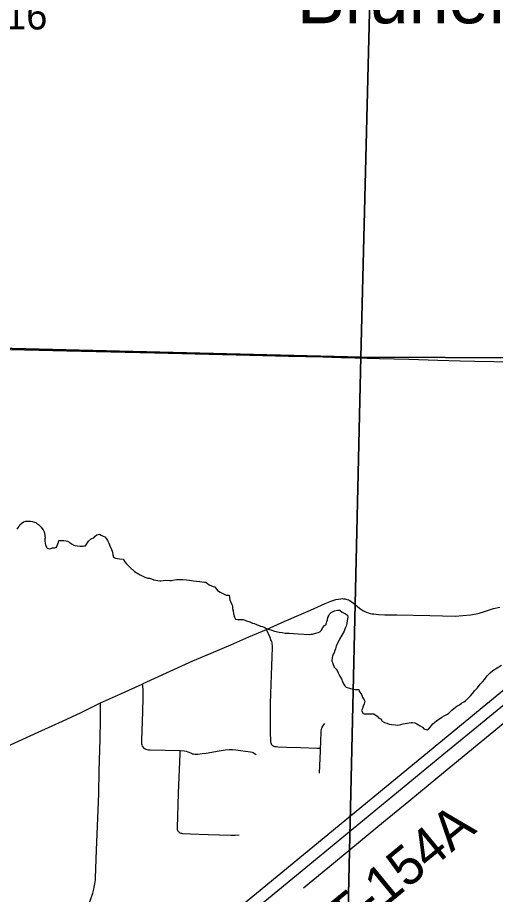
# Model space of a CAD drawing. Extents: x 0 to 34, y 0 to 22.
# Drawn here: x 3.956 to 4.659, y 18.651 to 19.941 of the extents above; entities that cross this region are included whole.
import ezdxf

# ---------------------------------------------------------------- set-up
doc = ezdxf.new("R2010")
doc.units = 0
for name, color, linetype in [('GM_X_Minor_River', 7, 'Continuous'), ('GM_X_Section', 7, 'Continuous'), ('GM_X_Section_Text', 7, 'Continuous'), ('GM_X_Township_Road', 7, 'Continuous'), ('GM_X_Township_Road_Text', 7, 'Continuous'), ('GM_X_Unincorporated_Text', 7, 'Continuous'), ('GM_X_US_Route', 7, 'Continuous')]:
    doc.layers.add(name, color=color, linetype=linetype)

msp = doc.modelspace()

# ---------------------------------------------------------------- linework, layer by layer
at = {"layer": 'GM_X_Minor_River'}
for points in [[(3.9553, 19.1884), (3.958, 19.1921), (3.9596, 19.1947), (3.9627, 19.1981), (3.9647, 19.1992), (3.9681, 19.2002), (3.97, 19.2002), (3.9723, 19.2001), (3.9749, 19.2001), (3.9776, 19.1996), (3.981, 19.1988), (3.9829, 19.1983), (3.9847, 19.1964), (3.987, 19.1952), (3.9888, 19.1933), (3.9907, 19.1917), (3.9918, 19.1898), (3.9936, 19.1874), (3.9951, 19.1847), (3.9961, 19.1794), (3.9964, 19.176), (3.9963, 19.1741), (3.9962, 19.1707), (3.9966, 19.168), (3.9969, 19.1649), (3.9994, 19.1607), (4.0036, 19.1595), (4.0074, 19.1609), (4.0104, 19.1612), (4.0131, 19.1619), (4.0143, 19.1645), (4.016, 19.1694), (4.0168, 19.1717)], [(4.0168, 19.1717), (4.0202, 19.1719), (4.024, 19.1719), (4.0274, 19.1714), (4.0293, 19.171), (4.0327, 19.169), (4.0353, 19.167), (4.0386, 19.165), (4.0409, 19.1646), (4.0439, 19.1638), (4.0481, 19.1636), (4.0515, 19.1636), (4.0534, 19.1639), (4.0557, 19.1642), (4.0601, 19.1709), (4.0647, 19.1746), (4.0682, 19.176), (4.0701, 19.1783), (4.0728, 19.1801), (4.0767, 19.1812), (4.0789, 19.1796), (4.0819, 19.1784), (4.0845, 19.1772), (4.0867, 19.1744), (4.0882, 19.1717), (4.09, 19.1679), (4.0921, 19.1629), (4.0939, 19.1587), (4.095, 19.1564), (4.0954, 19.1545), (4.096, 19.1507), (4.0971, 19.1476), (4.1001, 19.146), (4.1061, 19.1451), (4.1114, 19.1442), (4.1136, 19.1407), (4.1162, 19.1376), (4.1181, 19.1357), (4.121, 19.1326), (4.1281, 19.1263), (4.1363, 19.1212), (4.1434, 19.1179), (4.1476, 19.1167), (4.1499, 19.1163), (4.1529, 19.1154), (4.1563, 19.1142), (4.165, 19.1128), (4.1669, 19.1128), (4.1737, 19.1134), (4.1798, 19.1132), (4.1824, 19.1131), (4.1844, 19.1135), (4.1897, 19.1145), (4.1988, 19.1146), (4.2045, 19.1141), (4.209, 19.1136), (4.2147, 19.1127), (4.2193, 19.1122), (4.2238, 19.1117), (4.2268, 19.1113), (4.231, 19.1108), (4.2329, 19.1107), (4.2377, 19.1068), (4.2438, 19.1044), (4.246, 19.1039), (4.2501, 19.0985), (4.2538, 19.0958), (4.2587, 19.0934), (4.2628, 19.0917), (4.267, 19.0913), (4.268, 19.0844), (4.2705, 19.0786), (4.2719, 19.0759), (4.2722, 19.0721), (4.2729, 19.0683), (4.2735, 19.0638), (4.2749, 19.0592), (4.2767, 19.0561), (4.2798, 19.0556), (4.2843, 19.0555), (4.2877, 19.0558), (4.2926, 19.0538), (4.2975, 19.0521), (4.3013, 19.0505), (4.3039, 19.0497), (4.3062, 19.0489), (4.3084, 19.0477), (4.3111, 19.0468), (4.3133, 19.046), (4.3164, 19.0452), (4.3186, 19.0444), (4.3212, 19.0428), (4.3246, 19.0416), (4.3284, 19.0403), (4.334, 19.0383), (4.3405, 19.037), (4.345, 19.0365), (4.3495, 19.0356), (4.3556, 19.0355), (4.3617, 19.0349), (4.3685, 19.0344)], [(4.3685, 19.0344), (4.3856, 19.0336), (4.3879, 19.0339), (4.3898, 19.0342), (4.3924, 19.0349), (4.3947, 19.0356), (4.3978, 19.0367), (4.4005, 19.0374), (4.4024, 19.0396), (4.4048, 19.0437), (4.4072, 19.0467), (4.4091, 19.0478), (4.4103, 19.0508), (4.4107, 19.0527), (4.4116, 19.0553), (4.4124, 19.0587), (4.4136, 19.061), (4.4148, 19.0636), (4.4172, 19.0662), (4.4222, 19.0683), (4.4264, 19.0694), (4.4298, 19.0693), (4.4335, 19.0665), (4.4384, 19.0638), (4.4414, 19.0622), (4.4417, 19.0591), (4.4408, 19.0542), (4.4403, 19.0497), (4.4395, 19.0478), (4.4391, 19.0459), (4.4378, 19.0429), (4.4362, 19.0387), (4.4295, 19.0268), (4.4275, 19.0223), (4.4251, 19.0181), (4.4243, 19.0163), (4.4234, 19.0125), (4.4226, 19.0102), (4.4214, 19.0068), (4.4202, 19.0046), (4.4193, 19.0019), (4.4185, 18.9997), (4.418, 18.9951), (4.4195, 18.9909), (4.4216, 18.9856), (4.4246, 18.9828), (4.426, 18.9809), (4.4275, 18.9774), (4.43, 18.9724), (4.4322, 18.9686), (4.4336, 18.9647), (4.4354, 18.9609), (4.4372, 18.9582), (4.4391, 18.9563), (4.4455, 18.9542), (4.4531, 18.9529), (4.458, 18.9527), (4.4583, 18.9505), (4.4616, 18.9454), (4.4638, 18.9404), (4.4656, 18.9374), (4.4667, 18.9354), (4.4658, 18.9316), (4.4642, 18.9283), (4.463, 18.9249), (4.4618, 18.9219), (4.464, 18.9176), (4.4658, 18.9168), (4.4689, 18.9171), (4.4715, 18.9171), (4.4769, 18.9169), (4.4799, 18.9169), (4.4847, 18.9133), (4.4873, 18.9106), (4.4903, 18.9094), (4.4922, 18.9063), (4.4955, 18.9043), (4.4989, 18.9031), (4.5023, 18.9019), (4.5061, 18.901), (4.5118, 18.9005), (4.5148, 18.9004), (4.5175, 18.9007), (4.5198, 18.9014), (4.5228, 18.9021), (4.5347, 18.9041), (4.5369, 18.9044), (4.54, 18.9036), (4.5433, 18.9023), (4.5456, 18.9008), (4.5482, 18.8992), (4.5512, 18.8972), (4.5534, 18.8949), (4.5583, 18.8932), (4.5602, 18.8943), (4.5634, 18.8977), (4.5649, 18.8999), (4.5665, 18.9021), (4.5692, 18.9043), (4.5727, 18.9069), (4.5762, 18.9095)], [(4.5762, 18.9095), (4.5797, 18.9121), (4.5831, 18.9142), (4.5854, 18.9149), (4.5874, 18.916), (4.5897, 18.9175), (4.5916, 18.9193), (4.5944, 18.9223), (4.5975, 18.9249), (4.6021, 18.9282), (4.6056, 18.9304), (4.6087, 18.9326), (4.6121, 18.9344), (4.6145, 18.9359), (4.616, 18.9377), (4.6187, 18.9399), (4.6219, 18.9433), (4.625, 18.9466), (4.6285, 18.9511), (4.6324, 18.9552), (4.636, 18.9604), (4.6399, 18.9641), (4.643, 18.9678), (4.6465, 18.9726), (4.6508, 18.9771), (4.6551, 18.9808), (4.6678, 18.9884)]]:
    msp.add_lwpolyline(points, dxfattribs=at)
at = {"layer": 'GM_X_Section'}
for points in [[(3.4792, 20.4707), (4.4862, 20.4566), (4.461, 19.4414), (3.4549, 19.4664)], [(4.4862, 20.4566), (5.4829, 20.4382), (5.4561, 19.4374), (4.461, 19.4414)], [(3.4549, 19.4664), (4.461, 19.4414), (4.4379, 18.4375), (3.4283, 18.4755)], [(4.461, 19.4414), (5.4561, 19.4374), (5.435, 18.4221), (4.4379, 18.4375)]]:
    msp.add_lwpolyline(points, close=True, dxfattribs=at)
at = {"layer": 'GM_X_Township_Road'}
for points in [[(3.4581, 19.4645), (3.4734, 19.4643), (3.5107, 19.4638), (3.5685, 19.4624), (3.6381, 19.4604), (3.7214, 19.4586), (3.7797, 19.4572), (3.8419, 19.4557), (3.9158, 19.4536), (3.9457, 19.4529), (4.0283, 19.4507), (4.1576, 19.4477), (4.2576, 19.4453), (4.2974, 19.4446), (4.3546, 19.4431), (4.4049, 19.4419), (4.4312, 19.4412)], [(4.4312, 19.4412), (4.4341, 19.4411), (4.4882, 19.4397), (4.5311, 19.4384), (4.5739, 19.4372)], [(4.5739, 19.4372), (4.6068, 19.4363), (4.6286, 19.4358), (4.7678, 19.4333), (4.7695, 19.4332), (4.7714, 19.433), (4.7732, 19.4326), (4.7758, 19.4315), (4.777, 19.4309), (4.7789, 19.4296)], [(4.322, 19.0411), (4.3435, 19.0506), (4.3628, 19.0591), (4.3868, 19.0695), (4.4083, 19.0791), (4.4181, 19.083), (4.424, 19.0849), (4.4281, 19.0858), (4.4315, 19.0863), (4.4335, 19.0864), (4.4354, 19.0863), (4.4371, 19.0861), (4.4389, 19.0857), (4.4406, 19.0852), (4.4425, 19.0844), (4.4445, 19.0834), (4.4464, 19.082), (4.4498, 19.0795), (4.4589, 19.0722), (4.4636, 19.0689), (4.4664, 19.0674), (4.4689, 19.0663), (4.4717, 19.0653), (4.4744, 19.0646), (4.4768, 19.0642), (4.4801, 19.0638), (4.4869, 19.0632), (4.4962, 19.0627), (4.5137, 19.0625), (4.5621, 19.0614), (4.5997, 19.0607), (4.6222, 19.0626), (4.6331, 19.0646), (4.6442, 19.0679), (4.656, 19.0717), (4.6653, 19.0739)], [(4.1391, 18.9607), (4.1408, 18.9615), (4.1802, 18.9798), (4.2138, 18.9947), (4.2406, 19.0062), (4.2698, 19.0186), (4.2961, 19.03), (4.322, 19.0411)], [(4.3309, 18.8703), (4.3303, 18.8708), (4.3296, 18.872), (4.3293, 18.8727), (4.329, 18.8734), (4.3288, 18.8742), (4.3286, 18.8754), (4.3284, 18.8771), (4.3277, 18.8896), (4.3279, 18.9326), (4.3298, 18.9873), (4.3304, 19.0009), (4.3309, 19.0146), (4.3308, 19.0172), (4.3305, 19.0193), (4.3302, 19.0215), (4.3297, 19.0234), (4.3286, 19.026), (4.3274, 19.0292), (4.322, 19.0411)], [(4.078, 18.9331), (4.1044, 18.9449), (4.1391, 18.9607)], [(4.1391, 18.9607), (4.1397, 18.958), (4.1399, 18.9561), (4.1401, 18.9538), (4.1401, 18.9403), (4.1397, 18.9204), (4.1382, 18.8776), (4.1382, 18.8758), (4.1385, 18.8728), (4.1388, 18.8711), (4.1393, 18.8696), (4.1401, 18.8682), (4.1413, 18.867), (4.1427, 18.8659), (4.1444, 18.8651), (4.1465, 18.8645), (4.1486, 18.8642), (4.1508, 18.864), (4.1951, 18.8632)], [(3.693, 18.7944), (3.694, 18.7945), (3.7088, 18.7964), (3.7316, 18.7994), (3.7544, 18.8028), (3.7691, 18.8053), (3.7801, 18.8075), (3.7916, 18.8104), (3.8036, 18.8138), (3.8154, 18.8177), (3.83, 18.8231), (3.8912, 18.8478), (3.9221, 18.8608), (3.9522, 18.8742), (3.9918, 18.8922), (4.0223, 18.9063), (4.0493, 18.9191), (4.078, 18.9331)], [(4.0465, 18.5934), (4.0503, 18.6052), (4.0535, 18.6159), (4.0595, 18.6336), (4.0632, 18.6435), (4.0665, 18.6529), (4.0682, 18.6588), (4.0688, 18.6618), (4.0697, 18.6667), (4.0706, 18.6726), (4.0708, 18.6757), (4.072, 18.7164), (4.0753, 18.7997), (4.0761, 18.8333), (4.0774, 18.8799), (4.078, 18.9079), (4.0782, 18.9203), (4.078, 18.9331)], [(4.3763, 18.661), (4.4122, 18.6906), (4.4943, 18.7582), (4.5314, 18.7885), (4.574, 18.8237), (4.6182, 18.86), (4.6977, 18.9252)], [(4.4016, 18.8665), (4.4018, 18.8754), (4.4026, 18.8919), (4.403, 18.8941), (4.4034, 18.8958), (4.404, 18.8974), (4.4047, 18.8988), (4.4057, 18.9002), (4.4076, 18.9026)], [(4.2817, 18.7385), (4.276, 18.7382), (4.2698, 18.738), (4.2363, 18.7391), (4.2101, 18.7398), (4.1991, 18.7405), (4.1977, 18.7407), (4.1964, 18.7411), (4.1953, 18.7416), (4.1942, 18.7422), (4.1934, 18.7428), (4.1927, 18.7434), (4.1922, 18.7443), (4.1918, 18.7451), (4.1914, 18.746), (4.1913, 18.7472), (4.1914, 18.7492), (4.1929, 18.8001), (4.1949, 18.8579), (4.1951, 18.8632)], [(4.1951, 18.8632), (4.2008, 18.8624), (4.2039, 18.8618), (4.2063, 18.861), (4.2117, 18.8589), (4.2134, 18.8583), (4.2149, 18.858), (4.2167, 18.8577), (4.2209, 18.8578), (4.2276, 18.8584), (4.2331, 18.8592), (4.2527, 18.8626), (4.2613, 18.864), (4.267, 18.8645), (4.272, 18.8645), (4.277, 18.8641), (4.2838, 18.8628), (4.2985, 18.8609), (4.3011, 18.8603), (4.3029, 18.8596), (4.3052, 18.8581), (4.3071, 18.8565)], [(4.3309, 18.8703), (4.3319, 18.8697), (4.3327, 18.8694), (4.3338, 18.8691), (4.3348, 18.8689), (4.3361, 18.8687), (4.3385, 18.8686), (4.3515, 18.8681), (4.3719, 18.8674), (4.396, 18.8666), (4.4016, 18.8665)], [(4.4001, 18.8295), (4.4015, 18.8624), (4.4016, 18.8665)]]:
    msp.add_lwpolyline(points, dxfattribs=at)
at = {"layer": 'GM_X_US_Route'}
for points in [[(3.9649, 18.3719), (4.1388, 18.5144), (4.8134, 19.0696), (5.3507, 19.5121), (5.3793, 19.5364), (5.4865, 19.6225), (5.5411, 19.6666), (5.5871, 19.7051), (5.619, 19.7314), (5.639, 19.7465), (5.6887, 19.7879), (5.718, 19.8123)], [(3.9794, 18.3619), (4.0451, 18.4159), (4.1028, 18.4631), (4.1489, 18.5011), (4.3745, 18.6867), (4.4744, 18.7688), (4.5829, 18.8582), (4.7042, 18.9575)]]:
    msp.add_lwpolyline(points, dxfattribs=at)

# ---------------------------------------------------------------- texts
at = {"layer": 'GM_X_Section_Text'}
msp.add_text('16', height=0.04186, rotation=0, dxfattribs=at).set_placement((3.9376, 19.9236))
at = {"layer": 'GM_X_Township_Road_Text'}
msp.add_text('T-154A', height=0.05682, rotation=39.335, dxfattribs=at).set_placement((4.4403, 18.5865))
at = {"layer": 'GM_X_Unincorporated_Text'}
msp.add_text('Brunersburg', height=0.078977, rotation=0, dxfattribs=at).set_placement((4.3668, 19.9327))

doc.saveas('drawing.dxf')
